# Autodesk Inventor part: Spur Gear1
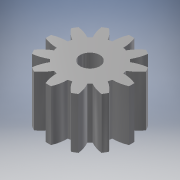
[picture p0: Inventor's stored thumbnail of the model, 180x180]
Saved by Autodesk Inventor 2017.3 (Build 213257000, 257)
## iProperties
Created: 2020-03
Part Number: Spur Gear1
Material: Steel
Document SubType Name: Modeling
Designer: Tim_G
Categories: <?xml version="1.0" encoding="UTF-16"?> <MemberInstance><Categories><FamilyTemplate><FamilyTemplateParameter ValueType="xs:double" Id="1" ObjectReferenceKey="da
Density: 1 g/cm^3
Appearance: Steel
CustomPartVersion: 1
Author: Tim_G
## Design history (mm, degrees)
sketch "Sketch1"
  geometry: C1 r 10.661 at (0, 0)
  constraints: 1 centre point
  dimensions: "d0" = 21.3211 diameter of C1 (= da_da)
extrude "Extrusion1" new body sketch "Sketch1" distance "d1" = 13 (= da_b); taper "d2" = 0 deg
workplane "Work Plane2"
sketch "Sketch2"
  geometry: C1 r 10.661 at (0, 0) reference; C2 r 9.138 at (0, 0)
  constraints: 1 centre point, 1 coincident
  dimensions: "d3" = 18.27523 diameter of C2 (= da_dw)
feature "Pitch Diameter" sketch "Sketch2" dims "d4" = 10, "d5" = 0
workplane "Work Plane8"
workplane "Work Plane9"
feature "Spur Gear" dims "d4" = 10, "da_b" = 13, "da_d" = 18.27523, "da_aw" = 27.41284, "da_da" = 21.3211, "da_df" = 14.46789, "da_dw" = 18.27523, angle "da_beta" = 0 deg, "da_lefttooth" = 0, "da_righttooth" = 0
sketch "Sketch3"
  geometry: C1 r 2.5 at (0, 0); 1 further point
  constraints: 1 centre point, 1 coincident
  dimensions: "d49" = 5 diameter of C1
extrude "Extrusion2" cut sketch "Sketch3" distance "d50" = 13; taper "d51" = 0 deg
body "Solid1"
body "Srf1"
other parameters: "d16" = 27.41284 (= da_aw), "d17" = 0, "d34" = 15 deg (computed from da_z), "d39" = 0, "d41" = 0, "d43" = 27.41284 (= da_aw), "d46" = 27.41284 (= da_aw), "d47" = 0, "d48" = 0
